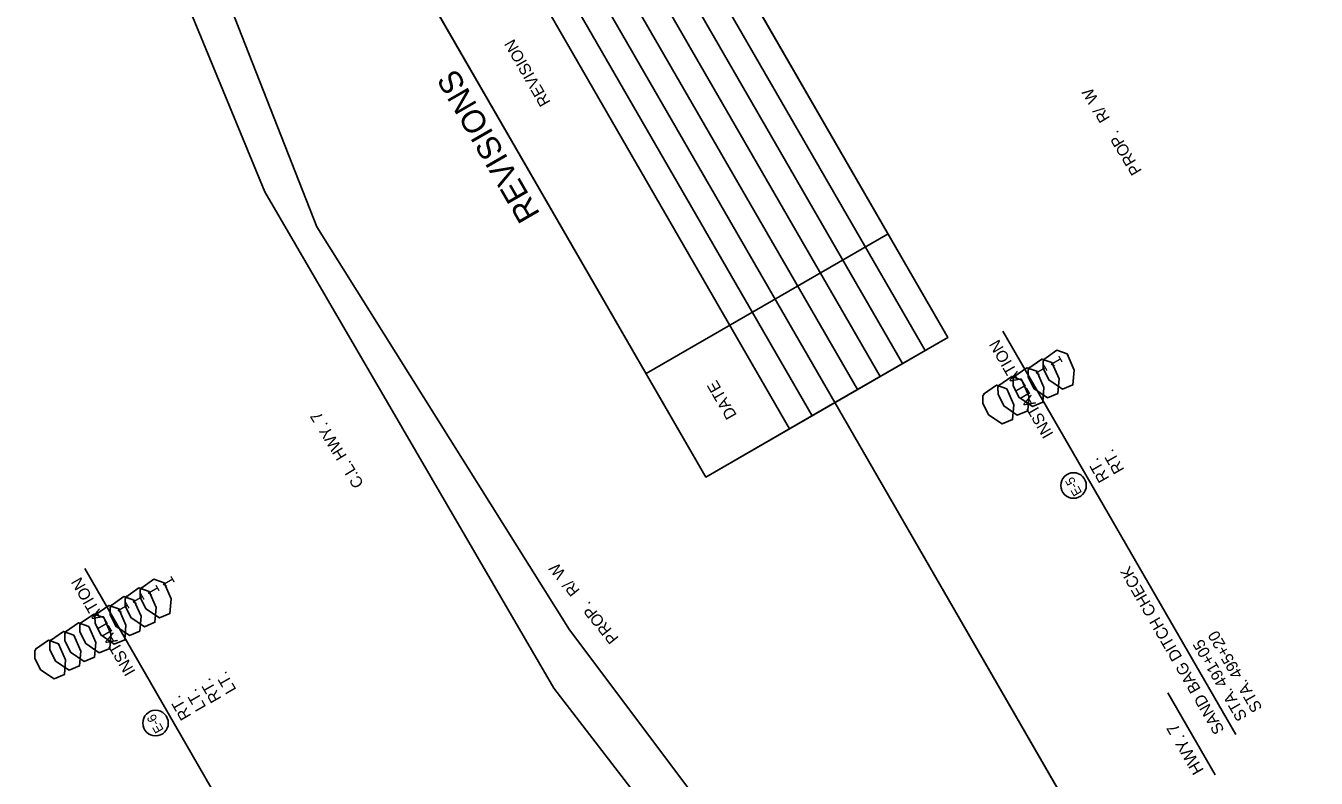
# Model space of a CAD drawing. Extents: x 956270 to 957915, y 1920520 to 1922423.
# Drawn here: x 956611 to 957278, y 1921340 to 1921729 of the extents above; entities that cross this region are included whole.
import ezdxf

# ---------------------------------------------------------------- set-up
doc = ezdxf.new("R2010")
doc.units = 0
for name, color, linetype in [('1', 7, 'Continuous'), ('44', 7, 'Continuous'), ('Default', 7, 'Continuous'), ('NO PLOT', 7, 'Continuous'), ('R_Draft', 7, 'Continuous'), ('S_TREE', 7, 'Continuous')]:
    doc.layers.add(name, color=color, linetype=linetype)

msp = doc.modelspace()

# ---------------------------------------------------------------- linework, layer by layer
at = {"layer": '1'}
msp.add_line((957172.25, 1921286.08), (957029.16, 1921533.92), dxfattribs=at)
for centre in [(957152.6, 1921491.06), (956677.88, 1921368.15)]:
    msp.add_circle(centre, 6.61, dxfattribs=at)
at = {"layer": '44'}
for p, q in [((957236.48, 1921362.24), (957115.97, 1921570.95)), ((956761.75, 1921239.33), (956641.25, 1921448.05)), ((957225.85, 1921341.45), (957201.43, 1921383.75))]:
    msp.add_line(p, q, dxfattribs=at)
at = {"layer": 'Default'}
for p, q in [((957087.62, 1921567.67), (956875.12, 1921935.73)), ((957075.93, 1921560.92), (956863.43, 1921928.98)), ((957064.24, 1921554.17), (956851.74, 1921922.23)), ((957052.55, 1921547.42), (956840.05, 1921915.48)), ((957040.85, 1921540.67), (956828.35, 1921908.73)), ((957040.85, 1921540.67), (956828.35, 1921908.73)), ((957029.16, 1921533.92), (956816.66, 1921901.98)), ((957017.47, 1921527.17), (956804.97, 1921895.23)), ((957005.78, 1921520.42), (956793.28, 1921888.48)), ((956962.48, 1921495.42), (956749.98, 1921863.48)), ((956931.57, 1921548.95), (957056.71, 1921621.2)), ((956962.48, 1921495.42), (957087.62, 1921567.67))]:
    msp.add_line(p, q, dxfattribs=at)
at = {"layer": 'NO PLOT'}
for points in [[(957915.18, 1921041.6), (957117.5, 1922423.23), (956666.17, 1922162.65), (956816.66, 1921901.98), (956875.12, 1921935.73), (957087.62, 1921567.67), (957029.16, 1921533.92), (957172.25, 1921286.08), (957225.74, 1921316.96), (957397.07, 1921020.21), (957343.58, 1920989.33), (957463.85, 1920781.02)], [(957915.18, 1921041.6), (957117.5, 1922423.23), (956666.17, 1922162.65), (956816.66, 1921901.98), (956875.12, 1921935.73), (957087.62, 1921567.67), (957029.16, 1921533.92), (957172.25, 1921286.08), (957225.74, 1921316.96), (957397.07, 1921020.21), (957343.58, 1920989.33), (957463.85, 1920781.02)], [(957915.18, 1921041.6), (957117.5, 1922423.23), (956666.17, 1922162.65), (956816.66, 1921901.98), (956875.12, 1921935.73), (957087.62, 1921567.67), (957029.16, 1921533.92), (957172.25, 1921286.08), (957225.74, 1921316.96), (957397.07, 1921020.21), (957343.58, 1920989.33), (957463.85, 1920781.02)], [(957012.51, 1920520.44), (956420.48, 1921545.87), (956463.26, 1921570.57), (956365.36, 1921740.14), (956378, 1921747.44), (956270.25, 1921934.07), (956666.17, 1922162.65), (956816.66, 1921901.98), (956749.98, 1921863.48), (956962.48, 1921495.42), (957029.16, 1921533.92), (957172.25, 1921286.08), (957120.9, 1921256.43), (957292.23, 1920959.68), (957343.58, 1920989.33), (957463.85, 1920781.02)], [(957012.51, 1920520.44), (956420.48, 1921545.87), (956463.26, 1921570.57), (956365.36, 1921740.14), (956378, 1921747.44), (956270.25, 1921934.07), (956666.17, 1922162.65), (956816.66, 1921901.98), (956749.98, 1921863.48), (956962.48, 1921495.42), (957029.16, 1921533.92), (957172.25, 1921286.08), (957120.9, 1921256.43), (957292.23, 1920959.68), (957343.58, 1920989.33), (957463.85, 1920781.02)], [(957012.51, 1920520.44), (956420.48, 1921545.87), (956463.26, 1921570.57), (956365.36, 1921740.14), (956378, 1921747.44), (956270.25, 1921934.07), (956666.17, 1922162.65), (956816.66, 1921901.98), (956749.98, 1921863.48), (956962.48, 1921495.42), (957029.16, 1921533.92), (957172.25, 1921286.08), (957120.9, 1921256.43), (957292.23, 1920959.68), (957343.58, 1920989.33), (957463.85, 1920781.02)]]:
    msp.add_lwpolyline(points, close=True, dxfattribs=at)
msp.add_lwpolyline([(956978.43, 1921300.96), (956891.96, 1921416.34), (956761.21, 1921624.84), (956685.68, 1921817.75), (956598.64, 1922001.42), (956569.16, 1922006.84), (956549.42, 1922003.64), (956496.56, 1922078), (956484.6, 1922065.05), (956487.74, 1922034.93), (956520.15, 1921988.76), (956538.43, 1921986.13), (956552.84, 1921975.42), (956577.89, 1921905.71), (956667.63, 1921797.4), (956675.52, 1921785.98), (956734.33, 1921642.98), (956883.87, 1921386.21), (956963.43, 1921282.81)], dxfattribs=at)
at = {"layer": 'S_TREE'}
for points in [[(957137.27, 1921556.23), (957144.02, 1921560.97), (957149.25, 1921559.11), (957152.9, 1921550.79), (957152.28, 1921543.19), (957146.88, 1921540.94), (957139.88, 1921545.68), (957136.93, 1921551.71), (957136.9, 1921555.41), (957137.86, 1921556.82)], [(957137.27, 1921556.23), (957144.02, 1921560.97), (957149.25, 1921559.11), (957152.9, 1921550.79), (957152.28, 1921543.19), (957146.88, 1921540.94), (957139.88, 1921545.68), (957136.93, 1921551.71), (957136.9, 1921555.41), (957137.86, 1921556.82)], [(957137.27, 1921556.23), (957144.02, 1921560.97), (957149.25, 1921559.11), (957152.9, 1921550.79), (957152.28, 1921543.19), (957146.88, 1921540.94), (957139.88, 1921545.68), (957136.93, 1921551.71), (957136.9, 1921555.41), (957137.86, 1921556.82)], [(957137.27, 1921556.23), (957144.02, 1921560.97), (957149.25, 1921559.11), (957152.9, 1921550.79), (957152.28, 1921543.19), (957146.88, 1921540.94), (957139.88, 1921545.68), (957136.93, 1921551.71), (957136.9, 1921555.41), (957137.86, 1921556.82)], [(957137.27, 1921556.23), (957144.02, 1921560.97), (957149.25, 1921559.11), (957152.9, 1921550.79), (957152.28, 1921543.19), (957146.88, 1921540.94), (957139.88, 1921545.68), (957136.93, 1921551.71), (957136.9, 1921555.41), (957137.86, 1921556.82)], [(957129.48, 1921551.73), (957136.23, 1921556.47), (957141.46, 1921554.61), (957145.11, 1921546.29), (957144.49, 1921538.69), (957139.09, 1921536.44), (957132.08, 1921541.18), (957129.13, 1921547.21), (957129.1, 1921550.91), (957130.06, 1921552.32)], [(957129.48, 1921551.73), (957136.23, 1921556.47), (957141.46, 1921554.61), (957145.11, 1921546.29), (957144.49, 1921538.69), (957139.09, 1921536.44), (957132.08, 1921541.18), (957129.13, 1921547.21), (957129.1, 1921550.91), (957130.06, 1921552.32)], [(957113.89, 1921542.73), (957120.64, 1921547.47), (957125.87, 1921545.61), (957129.52, 1921537.29), (957128.9, 1921529.69), (957123.5, 1921527.44), (957116.49, 1921532.18), (957113.54, 1921538.21), (957113.51, 1921541.91), (957114.48, 1921543.32)], [(957113.89, 1921542.73), (957120.64, 1921547.47), (957125.87, 1921545.61), (957129.52, 1921537.29), (957128.9, 1921529.69), (957123.5, 1921527.44), (957116.49, 1921532.18), (957113.54, 1921538.21), (957113.51, 1921541.91), (957114.48, 1921543.32)], [(957113.89, 1921542.73), (957120.64, 1921547.47), (957125.87, 1921545.61), (957129.52, 1921537.29), (957128.9, 1921529.69), (957123.5, 1921527.44), (957116.49, 1921532.18), (957113.54, 1921538.21), (957113.51, 1921541.91), (957114.48, 1921543.32)], [(957121.68, 1921547.23), (957128.44, 1921551.97), (957133.67, 1921550.11), (957137.32, 1921541.79), (957136.69, 1921534.19), (957131.3, 1921531.94), (957124.29, 1921536.68), (957121.34, 1921542.71), (957121.31, 1921546.41), (957122.27, 1921547.82)], [(957121.68, 1921547.23), (957128.44, 1921551.97), (957133.67, 1921550.11), (957137.32, 1921541.79), (957136.69, 1921534.19), (957131.3, 1921531.94), (957124.29, 1921536.68), (957121.34, 1921542.71), (957121.31, 1921546.41), (957122.27, 1921547.82)], [(957121.68, 1921547.23), (957128.44, 1921551.97), (957133.67, 1921550.11), (957137.32, 1921541.79), (957136.69, 1921534.19), (957131.3, 1921531.94), (957124.29, 1921536.68), (957121.34, 1921542.71), (957121.31, 1921546.41), (957122.27, 1921547.82)], [(957121.68, 1921547.23), (957128.44, 1921551.97), (957133.67, 1921550.11), (957137.32, 1921541.79), (957136.69, 1921534.19), (957131.3, 1921531.94), (957124.29, 1921536.68), (957121.34, 1921542.71), (957121.31, 1921546.41), (957122.27, 1921547.82)], [(957121.68, 1921547.23), (957128.44, 1921551.97), (957133.67, 1921550.11), (957137.32, 1921541.79), (957136.69, 1921534.19), (957131.3, 1921531.94), (957124.29, 1921536.68), (957121.34, 1921542.71), (957121.31, 1921546.41), (957122.27, 1921547.82)], [(957121.68, 1921547.23), (957128.44, 1921551.97), (957133.67, 1921550.11), (957137.32, 1921541.79), (957136.69, 1921534.19), (957131.3, 1921531.94), (957124.29, 1921536.68), (957121.34, 1921542.71), (957121.31, 1921546.41), (957122.27, 1921547.82)], [(957106.09, 1921538.23), (957112.85, 1921542.97), (957118.08, 1921541.11), (957121.73, 1921532.79), (957121.1, 1921525.19), (957115.71, 1921522.94), (957108.7, 1921527.68), (957105.75, 1921533.71), (957105.72, 1921537.41), (957106.68, 1921538.82)], [(957106.09, 1921538.23), (957112.85, 1921542.97), (957118.08, 1921541.11), (957121.73, 1921532.79), (957121.1, 1921525.19), (957115.71, 1921522.94), (957108.7, 1921527.68), (957105.75, 1921533.71), (957105.72, 1921537.41), (957106.68, 1921538.82)], [(956670.34, 1921437.83), (956677.09, 1921442.56), (956682.32, 1921440.7), (956685.97, 1921432.38), (956685.35, 1921424.78), (956679.95, 1921422.53), (956672.94, 1921427.27), (956670, 1921433.3), (956669.96, 1921437), (956670.93, 1921438.41)], [(956670.34, 1921437.83), (956677.09, 1921442.56), (956682.32, 1921440.7), (956685.97, 1921432.38), (956685.35, 1921424.78), (956679.95, 1921422.53), (956672.94, 1921427.27), (956670, 1921433.3), (956669.96, 1921437), (956670.93, 1921438.41)], [(956654.75, 1921428.83), (956661.5, 1921433.56), (956666.74, 1921431.7), (956670.38, 1921423.38), (956669.76, 1921415.78), (956664.37, 1921413.53), (956657.36, 1921418.27), (956654.41, 1921424.3), (956654.38, 1921428), (956655.34, 1921429.41)], [(956654.75, 1921428.83), (956661.5, 1921433.56), (956666.74, 1921431.7), (956670.38, 1921423.38), (956669.76, 1921415.78), (956664.37, 1921413.53), (956657.36, 1921418.27), (956654.41, 1921424.3), (956654.38, 1921428), (956655.34, 1921429.41)], [(956662.54, 1921433.33), (956669.3, 1921438.06), (956674.53, 1921436.2), (956678.18, 1921427.88), (956677.56, 1921420.28), (956672.16, 1921418.03), (956665.15, 1921422.77), (956662.2, 1921428.8), (956662.17, 1921432.5), (956663.13, 1921433.91)], [(956646.96, 1921424.33), (956653.71, 1921429.06), (956658.94, 1921427.2), (956662.59, 1921418.88), (956661.97, 1921411.28), (956656.57, 1921409.03), (956649.56, 1921413.77), (956646.61, 1921419.8), (956646.58, 1921423.5), (956647.55, 1921424.91)], [(956646.96, 1921424.33), (956653.71, 1921429.06), (956658.94, 1921427.2), (956662.59, 1921418.88), (956661.97, 1921411.28), (956656.57, 1921409.03), (956649.56, 1921413.77), (956646.61, 1921419.8), (956646.58, 1921423.5), (956647.55, 1921424.91)], [(956646.96, 1921424.33), (956653.71, 1921429.06), (956658.94, 1921427.2), (956662.59, 1921418.88), (956661.97, 1921411.28), (956656.57, 1921409.03), (956649.56, 1921413.77), (956646.61, 1921419.8), (956646.58, 1921423.5), (956647.55, 1921424.91)], [(956646.96, 1921424.33), (956653.71, 1921429.06), (956658.94, 1921427.2), (956662.59, 1921418.88), (956661.97, 1921411.28), (956656.57, 1921409.03), (956649.56, 1921413.77), (956646.61, 1921419.8), (956646.58, 1921423.5), (956647.55, 1921424.91)], [(956646.96, 1921424.33), (956653.71, 1921429.06), (956658.94, 1921427.2), (956662.59, 1921418.88), (956661.97, 1921411.28), (956656.57, 1921409.03), (956649.56, 1921413.77), (956646.61, 1921419.8), (956646.58, 1921423.5), (956647.55, 1921424.91)], [(956631.37, 1921415.33), (956638.12, 1921420.06), (956643.35, 1921418.2), (956647, 1921409.88), (956646.38, 1921402.28), (956640.98, 1921400.03), (956633.97, 1921404.77), (956631.03, 1921410.8), (956630.99, 1921414.5), (956631.96, 1921415.91)], [(956631.37, 1921415.33), (956638.12, 1921420.06), (956643.35, 1921418.2), (956647, 1921409.88), (956646.38, 1921402.28), (956640.98, 1921400.03), (956633.97, 1921404.77), (956631.03, 1921410.8), (956630.99, 1921414.5), (956631.96, 1921415.91)], [(956631.37, 1921415.33), (956638.12, 1921420.06), (956643.35, 1921418.2), (956647, 1921409.88), (956646.38, 1921402.28), (956640.98, 1921400.03), (956633.97, 1921404.77), (956631.03, 1921410.8), (956630.99, 1921414.5), (956631.96, 1921415.91)], [(956639.16, 1921419.83), (956645.92, 1921424.56), (956651.15, 1921422.7), (956654.8, 1921414.38), (956654.17, 1921406.78), (956648.78, 1921404.53), (956641.77, 1921409.27), (956638.82, 1921415.3), (956638.79, 1921419), (956639.75, 1921420.41)], [(956639.16, 1921419.83), (956645.92, 1921424.56), (956651.15, 1921422.7), (956654.8, 1921414.38), (956654.17, 1921406.78), (956648.78, 1921404.53), (956641.77, 1921409.27), (956638.82, 1921415.3), (956638.79, 1921419), (956639.75, 1921420.41)], [(956639.16, 1921419.83), (956645.92, 1921424.56), (956651.15, 1921422.7), (956654.8, 1921414.38), (956654.17, 1921406.78), (956648.78, 1921404.53), (956641.77, 1921409.27), (956638.82, 1921415.3), (956638.79, 1921419), (956639.75, 1921420.41)], [(956639.16, 1921419.83), (956645.92, 1921424.56), (956651.15, 1921422.7), (956654.8, 1921414.38), (956654.17, 1921406.78), (956648.78, 1921404.53), (956641.77, 1921409.27), (956638.82, 1921415.3), (956638.79, 1921419), (956639.75, 1921420.41)], [(956623.57, 1921410.83), (956630.33, 1921415.56), (956635.56, 1921413.7), (956639.21, 1921405.38), (956638.58, 1921397.78), (956633.19, 1921395.53), (956626.18, 1921400.27), (956623.23, 1921406.3), (956623.2, 1921410), (956624.16, 1921411.41)], [(956615.78, 1921406.33), (956622.53, 1921411.06), (956627.76, 1921409.2), (956631.41, 1921400.88), (956630.79, 1921393.28), (956625.39, 1921391.03), (956618.38, 1921395.77), (956615.44, 1921401.8), (956615.41, 1921405.5), (956616.37, 1921406.91)]]:
    msp.add_lwpolyline(points, dxfattribs=at)

# ---------------------------------------------------------------- texts
at = {"layer": '1'}
for s, p in [('E-5 ', (957157.16, 1921487.34)), ('E-6 ', (956682.28, 1921364.69))]:
    msp.add_text(s, height=4.8, rotation=120, dxfattribs=at).set_placement(p)
at = {"layer": '44'}
for s, height, p in [('INSTALLATION', 6, (957142.4, 1921517.67)), ('1', 6, (957139.48, 1921550.11)), ('1', 6, (957147.28, 1921554.61)), ('RT.', 6, (957179.05, 1921499.24)), ('RT.', 6, (957171.26, 1921494.74)), ('SAND BAG DITCH CHECK', 6, (957230.83, 1921364.51)), ('INSTALLATION', 6, (956667.68, 1921394.76)), ('1', 6, (956680.35, 1921436.2)), ('1', 6, (956688.14, 1921440.7)), ('1', 6, (956672.55, 1921431.7)), ('1', 6, (956664.76, 1921427.2)), ('STA. 495+20', 6, (957250.46, 1921375.85)), ('STA. 491+05', 6, (957242.67, 1921371.35)), ('LT.', 6, (956719.84, 1921385.46)), ('LT.', 6, (956704.25, 1921376.46)), ('RT.', 6, (956712.12, 1921380.83)), ('RT.', 6, (956696.53, 1921371.83)), ('HWY. 7', 6.25, (957220.16, 1921343.76))]:
    msp.add_text(s, height=height, rotation=120, dxfattribs=at).set_placement(p)
at = {"layer": 'Default'}
for s, height, p in [('REVISION', 6, (956882.3, 1921689.29)), ('REVISIONS', 12, (956876.99, 1921631.48)), ('DATE', 6, (956978.64, 1921527.43))]:
    msp.add_text(s, height=height, rotation=120, dxfattribs=at).set_placement(p)
at = {"layer": 'R_Draft'}
for s, rotation, p in [('W', 121.18992, (957165.68, 1921690.88)), ('/', 121.18992, (957168.72, 1921685.87)), ('R', 121.18992, (957171.65, 1921681.02)), ('.', 121.18992, (957176.28, 1921673.38)), ('P', 121.18992, (957179.21, 1921668.53)), ('O', 121.18992, (957182.25, 1921663.52)), ('R', 121.18992, (957185.18, 1921658.67)), ('P', 121.18992, (957188.12, 1921653.82)), ('C.L. HWY. 7', 121.35452, (956785.85, 1921491.94)), ('W', 129.14741, (956890.32, 1921445.72)), ('/', 129.14741, (956894.02, 1921441.17)), ('R', 129.14741, (956897.59, 1921436.78)), ('P', 129.14741, (956906.81, 1921425.46)), ('.', 129.14741, (956903.23, 1921429.85)), ('O', 129.14741, (956910.51, 1921420.91)), ('R', 129.14741, (956914.09, 1921416.52)), ('P', 129.14741, (956917.67, 1921412.12))]:
    msp.add_text(s, height=6, rotation=rotation, dxfattribs=at).set_placement(p)

doc.saveas('drawing.dxf')
